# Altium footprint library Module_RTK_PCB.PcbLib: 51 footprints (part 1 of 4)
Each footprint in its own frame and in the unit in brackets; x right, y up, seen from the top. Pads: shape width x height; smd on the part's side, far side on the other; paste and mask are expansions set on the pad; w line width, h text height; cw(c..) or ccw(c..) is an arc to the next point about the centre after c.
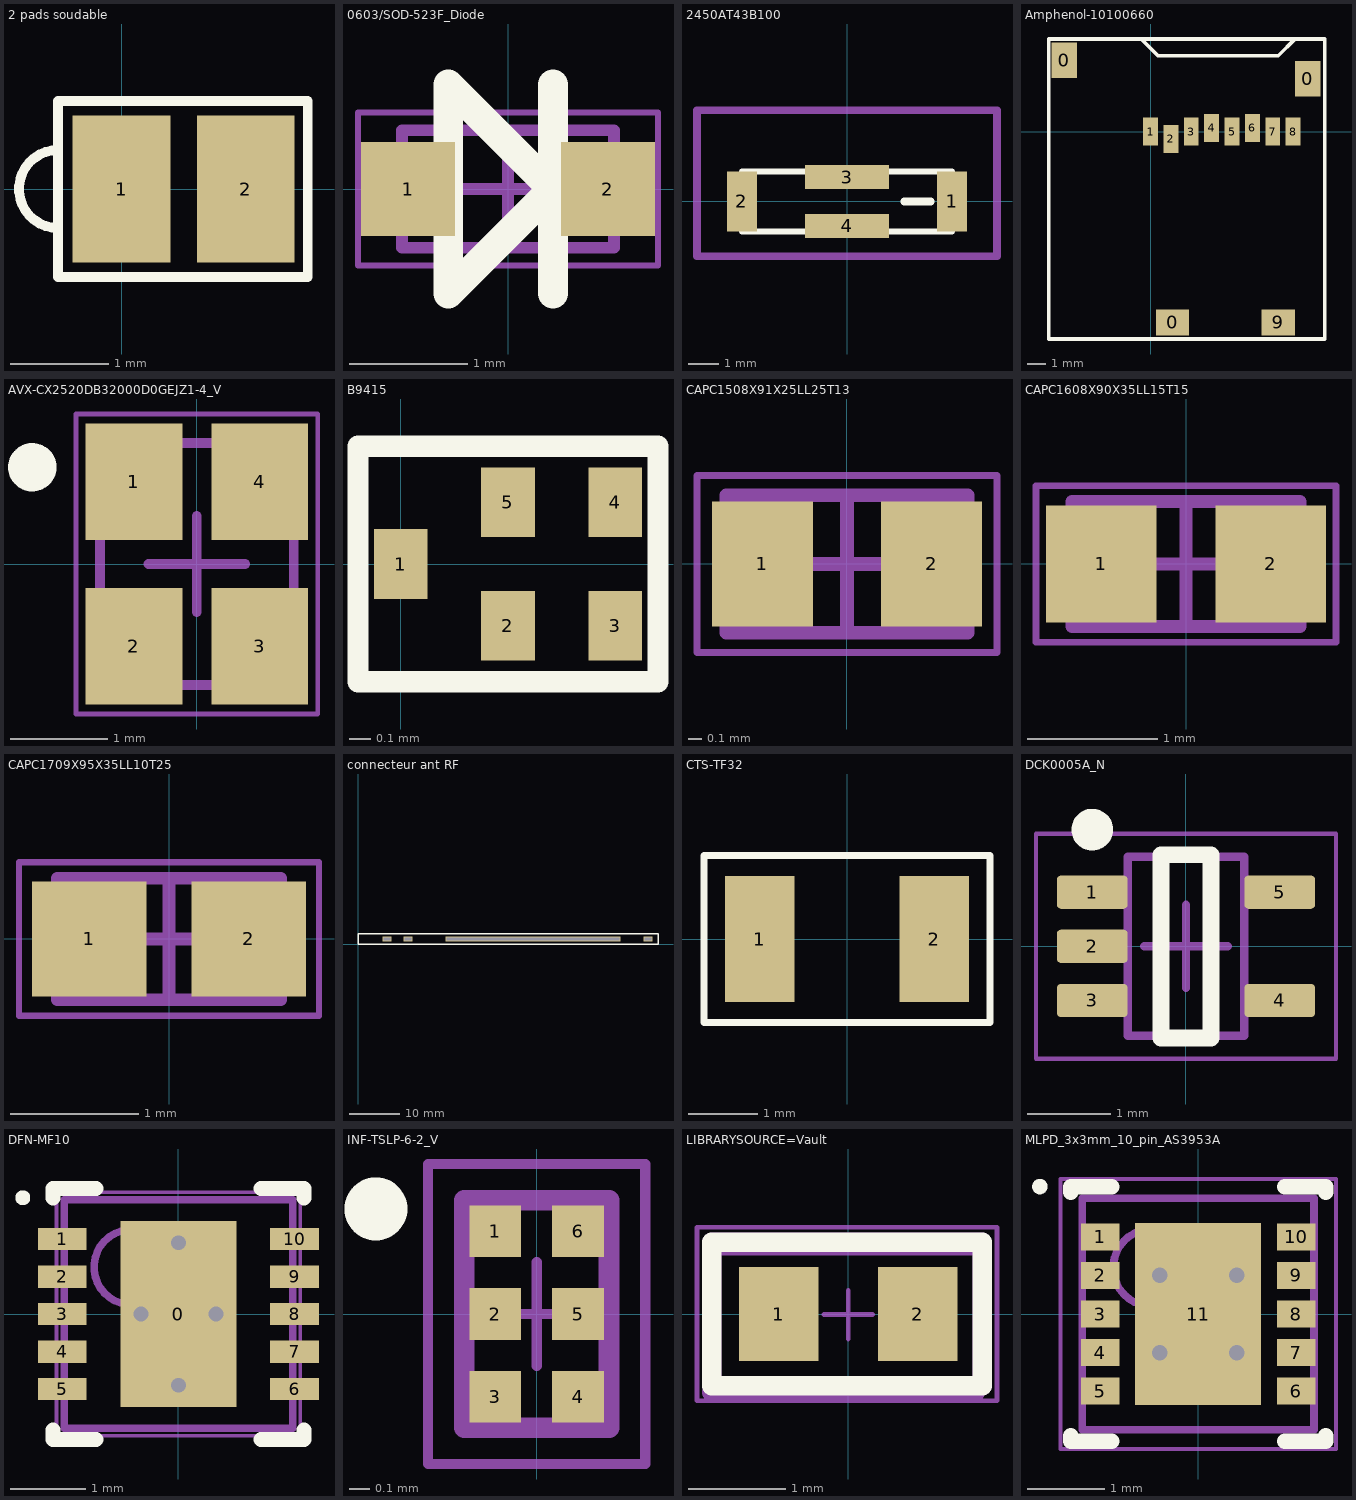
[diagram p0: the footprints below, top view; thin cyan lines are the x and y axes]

## 2 pads soudable [mm] "Connector; Header; 2 Position"
height 4.8
pads (2):
  rect 1x1.5 smd: 1(0,0) 2(1.27,0)
Top Overlay:
  lines w0.1: -0.65,-0.4 cw(c-0.65,0) -0.65,0.4 ; -0.65,-0.9 -0.65,0.9 1.905,0.9 1.905,-0.9 -0.65,-0.9

## 0603/SOD-523F_Diode [mm] "SODFL, 2-Leads, Body 0,90x1,70mm, IPC Medium Density"
height 0.85
pads (2):
  rect 0.8x0.8 smd: 1(-0.85,0) 2(0.85,0)
Top Overlay:
  lines w0.254: 0.381,-0.889 0.381,0.889 ; -0.508,-0.889 0.381,0 -0.508,0.889 -0.508,-0.889
Mechanical 13:
  lines w0.1: -0.9,-0.5 -0.9,0.5 0.9,0.5 0.9,-0.5 -0.9,-0.5
Mechanical 15:
  lines w0.05: -1.275,-0.65 -1.275,0.65 1.275,0.65 1.275,-0.65 -1.275,-0.65
  lines w0.1: -0.5,0 0.5,0 ; 0,-0.5 0,0.5
3D body: height 0.85, standoff 0, extent -0.9,-0.5 0.9,0.5

## 2450AT43B100 [mm] "ble ant 2.4 GHz"
pads (4):
  rect 1x2 smd: 1(3.5,0) 2(-3.5,0)
  rect 2.8x0.8 smd: 3(0,0.815) 4(0,-0.815)
Top Overlay:
  lines w0.2: -3.5,-1 3.5,-1 3.5,1 -3.5,1 -3.5,-1
  lines w0.254: 1.905,0 2.794,0
Mechanical 1:
  lines w0.254: -5,-1.825 -5,3.045 5,3.045 5,-1.825 -5,-1.825

## Amphenol-10100660 [mm] "Micro-SD"
height 2.36
pads (12):
  rect 1.4x1.9 smd: 0(-4.66,3.85) 0(8.49,2.85)
  rect 1.8x1.4 smd: 0(1.19,-10.3) 9(6.89,-10.3)
  rect 0.8x1.5 smd: 1(0,0) 2(1.1,-0.4) 3(2.2,0) 4(3.3,0.2) 5(4.4,0) 6(5.5,0.2) 7(6.6,0) 8(7.7,0)
Top Overlay:
  lines w0.2: 7.8,5 6.9,4.1 0.4,4.1 -0.5,5 ; -0.5,5 -0.5,5 ; -5.5,-11.2 9.4,-11.2 9.4,5 -5.5,5 -5.5,-11.2

## AVX-CX2520DB32000D0GEJZ1-4_V [mm] "Hand Drawn, 4-Leads,Body 2.5x2mm"
height 0.55
pads (4):
  rect 1x1.2 smd: 1(-0.65,0.85) 2(-0.65,-0.85) 3(0.65,-0.85) 4(0.65,0.85)
Top Overlay:
  circle w0.25: c-1.7,1 r0.125
Mechanical 13:
  lines w0.1: -1,-1.25 -1,1.25 1,1.25 1,-1.25 -1,-1.25
Mechanical 15:
  lines w0.05: -1.25,-1.55 -1.25,1.55 1.25,1.55 1.25,-1.55 -1.25,-1.55
  lines w0.1: -0.5,0 0.5,0 ; 0,-0.5 0,0.5
3D body: height 0.55, standoff 0, extent -1,-1.25 1,1.25

## B9415 [mm]
height 4.8
pads (5):
  rect 0.25x0.325 smd: 1(0,0) 2(0.5,-0.288) 3(1,-0.288) 4(1,0.288) 5(0.5,0.288)
Top Overlay:
  lines w0.1: -0.2,-0.55 1.2,-0.55 1.2,0.55 -0.2,0.55 -0.2,-0.55

## CAPC1508X91X25LL25T13 [mm] "Chip Capacitor, 2-Leads, Body 1.52x0.76mm, IPC High Density"
height 0.91
pads (2):
  rect 0.74x0.92 smd: 1(-0.62,0) 2(0.62,0)
Mechanical 13:
  lines w0.1: -0.885,-0.505 -0.885,0.505 0.885,0.505 0.885,-0.505 -0.885,-0.505
Mechanical 15:
  lines w0.05: -1.1,-0.65 -1.1,0.65 1.1,0.65 1.1,-0.65 -1.1,-0.65
  lines w0.1: -0.5,0 0.5,0 ; 0,-0.5 0,0.5
3D body: height 0.91, standoff 0, extent -0.635,-0.505 0.635,0.505
3D body: height 0.91, standoff 0, extent -0.885,-0.505 -0.635,0.505
3D body: height 0.91, standoff 0, extent 0.635,-0.505 0.885,0.505

## CAPC1608X90X35LL15T15 [mm] "Chip Capacitor, 2-Leads, Body 1.60x0.81mm, IPC High Density"
height 0.9
pads (2):
  rect 0.85x0.9 smd: 1(-0.65,0) 2(0.65,0)
Mechanical 13:
  lines w0.1: -0.875,-0.48 0.875,-0.48 0.875,0.48 -0.875,0.48 -0.875,-0.48
Mechanical 15:
  lines w0.05: -1.15,-0.6 1.15,-0.6 1.15,0.6 -1.15,0.6 -1.15,-0.6
  lines w0.1: -0.48,0 0.48,0 ; 0,-0.48 0,0.48
3D body: height 0.9, standoff 0, extent 0.525,-0.48 0.875,0.48
3D body: height 0.9, standoff 0, extent -0.875,-0.48 -0.525,0.48
3D body: height 0.9, standoff 0, extent -0.525,-0.48 0.525,0.48

## CAPC1709X95X35LL10T25 [mm] "Chip Capacitor, 2-Leads, Body 1.75x0.95mm, IPC High Density"
height 0.95
pads (2):
  rect 0.9x0.9 smd: 1(-0.625,0) 2(0.625,0)
Mechanical 13:
  lines w0.1: -0.875,-0.475 -0.875,0.475 0.875,0.475 0.875,-0.475 -0.875,-0.475
Mechanical 15:
  lines w0.05: -1.175,-0.6 -1.175,0.6 1.175,0.6 1.175,-0.6 -1.175,-0.6
  lines w0.1: -0.475,0 0.475,0 ; 0,-0.475 0,0.475
3D body "CAPC1608X10L.step": height 0.95, standoff 0, extent -0.875,-0.475 0.875,0.475

## connecteur ant RF [mm]
pads (4):
  rect 1.8x1 hole 0.6 slot 1.4 at 0 deg: 1(10,1) 2(5.8,1) 3(58,1)
  rect 35x1 hole 0.6 slot 34.6 at 0 deg: 2(35,1)
Top Overlay:
  lines w0.254: 0,0 0,2 60,2 60,0 0,0

## CTS-TF32 [mm] "3.2mm x 1.5mm"
pads (2):
  rect 1x1.8 smd: 1(-1.25,0) 2(1.25,0)
Top Overlay:
  lines w0.1: -2.05,-1.2 -2.05,0 -2.05,1.2 2.05,1.2 2.05,-1.2 -2.05,-1.2

## DCK0005A_N [mm] "SOT23, 5-Leads, Body 2.15x1.4mm, Pitch 0.65mm, IPC Medium Density"
height 1.1
pads (5):
  rrect25% 0.85x0.4 smd: 1(-1.125,0.65) 2(-1.125,0) 3(-1.125,-0.65) 4(1.125,-0.65) 5(1.125,0.65)
Top Overlay:
  circle w0.25: c-1.125,1.4 r0.125
  lines w0.2: -0.3,-1.1 -0.3,1.1 0.3,1.1 0.3,-1.1 -0.3,-1.1
Mechanical 1:
  text ".Designator" at -0.635,-0.127 h0.3
Mechanical 13:
  lines w0.1: -0.7,-1.075 0.7,-1.075 0.7,1.075 -0.7,1.075 -0.7,-1.075
Mechanical 15:
  lines w0.05: -1.8,-1.35 1.8,-1.35 1.8,1.35 -1.8,1.35 -1.8,-1.35
  lines w0.1: -0.5,0 0.5,0 ; 0,-0.5 0,0.5
3D body "DCK0005AakaMAA05A.stp": height 0.94, standoff -0.01, extent -1.14,-1 1.14,1

## DFN-MF10 [mm] "SON, 10-Leads, Body 3x3mm, Pitch 0.5mm, Microchip Recommended"
height 1
pads (11):
  rect 1.55x2.48 smd: 0(0,0)
  rect 0.65x0.3 smd: 1(-1.55,1) 2(-1.55,0.5) 3(-1.55,0) 4(-1.55,-0.5) 5(-1.55,-1) 6(1.55,-1) 7(1.55,-0.5) 8(1.55,0) 9(1.55,0.5) 10(1.55,1)
via 0,0.95 diameter 0.5 hole 0.2
via 0.5,0 diameter 0.5 hole 0.2
via 0,-0.95 diameter 0.5 hole 0.2
via -0.5,0 diameter 0.5 hole 0.2
Top Overlay:
  circle w0.1: c-2.075,1.55 r0.05
  lines w0.2: -1.675,-1.55 -1.675,-1.675 -1.1,-1.675 ; -1.675,1.55 -1.675,1.675 -1.1,1.675 ; 1.1,-1.675 1.675,-1.675 1.675,-1.55 ; 1.1,1.675 1.675,1.675 1.675,1.55
Mechanical 13:
  circle w0.1: c-0.625,0.625 r0.5
  lines w0.1: -1.525,-1.525 1.525,-1.525 1.525,1.525 -1.525,1.525 -1.525,-1.525
Mechanical 15:
  lines w0.05: -1.625,-1.625 -1.625,1.625 1.625,1.625 1.625,-1.625 -1.625,-1.625
  lines w0.1: -0.5,0 0.5,0 ; 0,-0.5 0,0.5
3D body: height 1, standoff 0, extent -1.524,-1.524 1.524,1.524

## INF-TSLP-6-2_V [mm] "TSLP, 6-Leads, Body 0.7x1.1 mm"
height 0.4
pads (6):
  rect 0.25x0.25 smd: 1(-0.2,0.4) 2(-0.2,0) 3(-0.2,-0.4) 4(0.2,-0.4) 5(0.2,0) 6(0.2,0.4)
Top Overlay:
  circle w0.254: c-0.777,0.508 r0.025
Mechanical 13:
  lines w0.1: -0.35,-0.55 0.35,-0.55 0.35,0.55 -0.35,0.55 -0.35,-0.55
Mechanical 15:
  lines w0.05: -0.25,0 0.25,0 ; 0,-0.25 0,0.25 ; -0.525,-0.725 0.525,-0.725 0.525,0.725 -0.525,0.725 -0.525,-0.725
3D body: height 0.4, standoff 0, extent -0.35,-0.55 0.35,0.55

## LIBRARYSOURCE=Vault [mil]
height 188.98
pads (2):
  rect 32x38 smd: 1(-28,0) 2(28,0)
Top Overlay:
  lines w7.87: -55,-29 -55,29 54,29 54,-29 -55,-29
Mechanical 11:
  lines w7.87: -55.12,-31.5 51.18,-31.5 ; -55.12,27.56 51.18,27.56
  text ".designator" at -55.12,-19.68 h39.37
Mechanical 13:
  lines w7.87: -55,-29 54,-29 54,29 -55,29 -55,-29
Mechanical 15:
  lines w1.97: -0.01,-0.26 -0.01,9.58 -0.01,-0.26 ; -0.01,-0.26 -9.85,-0.26 -0.01,-0.26 ; -0.01,-0.26 9.84,-0.26 -0.01,-0.26 ; -0.01,-0.26 -0.01,-10.1 -0.01,-0.26 ; -61,-35 60,-35 60,35 -61,35 -61,-35
3D body "User Library-cap_0603-1.STEP": height 31.5, standoff 0, extent -31.5,-16 31.5,15.49

## MLPD_3x3mm_10_pin_AS3953A [mm] "PSON, 10-Leads, Body 3,00x3,00mm, Pitch 0,50mm, Thermal Pad 2,36x1,63mm, IPC Medium Density"
height 1
pads (11):
  rect 0.5x0.35 smd: 1(-1.27,1) 2(-1.27,0.5) 3(-1.27,0) 4(-1.27,-0.5) 5(-1.27,-1) 6(1.27,-1) 7(1.27,-0.5) 8(1.27,0) 9(1.27,0.5) 10(1.27,1)
  rect 1.63x2.36 smd: 11(0,0)
via 0.5,-0.5 diameter 0.5 hole 0.2
via -0.5,-0.5 diameter 0.5 hole 0.2
via 0.5,0.5 diameter 0.5 hole 0.2
via -0.5,0.5 diameter 0.5 hole 0.2
Top Overlay:
  circle w0.1: c-2.05,1.65 r0.05
  lines w0.2: -1.65,-1.575 -1.65,-1.65 -1.12,-1.65 ; -1.65,1.575 -1.65,1.65 -1.12,1.65 ; 1.12,-1.65 1.65,-1.65 1.65,-1.575 ; 1.12,1.65 1.65,1.65 1.65,1.575
Mechanical 13:
  circle w0.1: c-0.6,0.6 r0.5
  lines w0.1: -1.5,-1.5 1.5,-1.5 1.5,1.5 -1.5,1.5 -1.5,-1.5
Mechanical 15:
  lines w0.05: -1.785,-1.75 1.785,-1.75 1.785,1.75 -1.785,1.75 -1.785,-1.75
  lines w0.1: -0.5,0 0.5,0 ; 0,-0.5 0,0.5
3D body: height 1, standoff 0.05, extent -1.5,-1.5 1.5,1.5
